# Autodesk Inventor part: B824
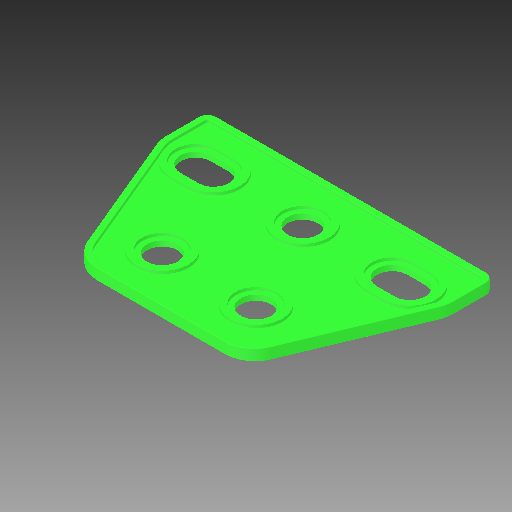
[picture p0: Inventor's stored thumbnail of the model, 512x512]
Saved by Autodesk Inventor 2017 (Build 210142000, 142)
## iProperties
Part Number: B824
Material: Générique
Document SubType Name: Modeling
Designer: ficho
Density: 1 g/cm^3
Appearance: Par défaut
Author: ficho
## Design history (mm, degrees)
feature "Solid1"
node "Solide1"
